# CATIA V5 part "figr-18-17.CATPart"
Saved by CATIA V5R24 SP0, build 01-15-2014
Part number: Part1
Bounding box of the stored display mesh (mm): x -145.664 to 56.336, y -59.016 to 59.016, z 0 to 59.016
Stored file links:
  D:\KAVITA\CATIA V5-6R2014 Project_ Kavita\CATIA V5-6R2014_partfiles\Partfiles\c17_caia_v6-6r2014_prt\figr-17-17.CATPart
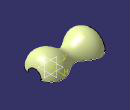
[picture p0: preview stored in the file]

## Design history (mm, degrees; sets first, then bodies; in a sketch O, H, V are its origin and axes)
Body1 (main body)
  Sketch1 on xy-plane, origin (0, 0, 0), H (0, 1, 0), V (-1, 0, 0)
    axis line L1 (0, 123.8615) -> (0, -59.1385)
    point P1 (0, 123.8615)
    point P3 (0, -34.0335)
    spline S1 through (23.6546, -56.3365) (51.0796, -40.3365) (54.2281, 7) (30.2281, 53.4991) (54.2281, 100.4991) (46.6546, 145.6635)
    coincidence: P1 V, P3 L1
    vertical: L1 V
  Revol1: Element1 Sketch1, Angle1 180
